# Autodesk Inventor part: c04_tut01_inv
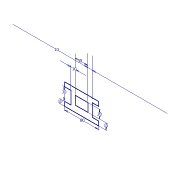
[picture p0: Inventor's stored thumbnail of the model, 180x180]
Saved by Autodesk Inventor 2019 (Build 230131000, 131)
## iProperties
Created: 2017-04
Part Number: c04_tut01_inv
Material: Generic
Document SubType Name: Modeling
Designer: CADCIM 00
Density: 1 g/cm^3
Appearance: Default
Author: CADCIM 00
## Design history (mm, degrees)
sketch "Sketch1"
  geometry: 1 further point
sketch "Sketch2"
  geometry: L1 (0, 0)-(0, 10); L2 (0, 10)-(-15, 10); L3 (-15, 10)-(-15, 40); L4 (-15, 40)-(0, 40); L5 (0, 40)-(0, 50); L6 (0, 50)-(-80, 50); L7 (-80, 50)-(-80, 40); L8 (-80, 40)-(-65, 40); L9 (-65, 40)-(-65, 10); L10 (-65, 10)-(-80, 10); L11 (-80, 0)-(0, 0); L12 (-80, 10)-(-80, 0); L13 (-25, 35)-(-55, 35); L14 (-55, 35)-(-55, 15); L15 (-55, 15)-(-25, 15); L16 (-25, 15)-(-25, 35)
  constraints: 32 end point, 8 perpendicular, 8 point on line, 3 parallel, 2 collinear, 1 horizontal, 1 vertical
  dimensions: "d0" = 80 distance of L11.start L1.start; "d1" = 10 distance of L1.start L1.end; "d2" = 30 distance of L2.end L3.end; "d3" = 10 distance between parallel lines of L16 L3; "d4" = 10 distance between parallel lines of L9 L14; "d5" = 15 distance between parallel lines of L15 L11; "d6" = 20 distance of L13.end L14.end; "d7" = 30 distance of L13.start L13.end
